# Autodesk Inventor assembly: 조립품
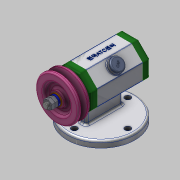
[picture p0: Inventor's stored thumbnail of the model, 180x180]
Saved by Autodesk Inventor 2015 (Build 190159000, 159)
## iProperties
Created: 2021-02
Part Number: 조립품
Document SubType Name: Assembly
Designer: Administrator
Author: Administrator
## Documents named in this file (14)
- C:\Users\Administrator\Desktop\710204V1012\조립품.iam
- C:\Users\Administrator\Desktop\710204V1012\본체.ipt
- C:\Users\Administrator\Desktop\710204V1012\베어링 15 x 32 x 9.ipt
- C:\Users\Administrator\Desktop\710204V1012\뒤커버.ipt
- C:\Users\Administrator\Desktop\710204V1012\앞커버.ipt
- C:\Users\Administrator\Desktop\710204V1012\볼트 M4 x 12.ipt
- C:\Users\Administrator\Desktop\710204V1012\축.ipt
- C:\Users\Administrator\Desktop\710204V1012\키 3 x 3 x 12.ipt
- C:\Users\Administrator\Desktop\710204V1012\오일 실 15 25 7.ipt
- C:\Users\Administrator\Desktop\710204V1012\V벨트풀리.ipt
- C:\Users\Administrator\Desktop\710204V1012\와셔 8x17.ipt
- C:\Users\Administrator\Desktop\710204V1012\스프링와셔 8.ipt
- C:\Users\Administrator\Desktop\710204V1012\너트 M8.ipt
- C:\Users\Administrator\Desktop\710204V1012\고무캡.ipt
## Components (2 placed, 2 different names)
1. V벨트풀리:1
2. 고무캡:1
